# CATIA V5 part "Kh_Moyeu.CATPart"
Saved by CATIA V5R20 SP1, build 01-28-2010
Part number: Moyeu
Bounding box of the stored display mesh (mm): x -31.991 to 31.991, y -32 to 32, z -27 to 27
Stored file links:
  G:\Khaled_CFAO_2011\SIL\SIL_GR1\tmerino\Khaled\CAD_Thinkmotion\Kh_Moyeu.CATPart
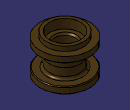
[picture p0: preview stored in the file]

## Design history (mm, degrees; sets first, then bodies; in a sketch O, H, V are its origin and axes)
Body1 (main body)
  Sketch1 on yz-plane, origin (0, 0, 0), H (0, 1, 0), V (0, 0, 1)
    line L1 (13, 0) -> (13, 15)
    point P1 (13, 0)
    point P2 (13, 15)
    line L2 (13, 15) -> (20, 15)
    point P3 (20, 15)
    line L3 (20, 15) -> (20, 27)
    point P4 (20, 27)
    line L4 (20, 27) -> (24, 27)
    point P5 (24, 27)
    line L5 (24, 27) -> (24, 21)
    point P6 (24, 21)
    line L6 (24, 21) -> (32, 21)
    point P7 (32, 21)
    line L7 (32, 21) -> (32, 13)
    point P8 (32, 13)
    line L8 (32, 13) -> (20, 13)
    point P9 (20, 13)
    line L9 (20, 13) -> (20, 0)
    point P10 (20, 0)
    point P11 (13, 0)
    point P12 (13, -15)
    point P13 (20, -15)
    point P14 (20, -27)
    point P15 (24, -27)
    point P16 (24, -21)
    point P17 (32, -21)
    point P18 (32, -13)
    point P19 (20, -13)
    point P20 (20, 0)
    line L10 (13, 0) -> (13, -15)
    line L11 (13, -15) -> (20, -15)
    line L12 (20, -15) -> (20, -27)
    line L13 (20, -27) -> (24, -27)
    line L14 (24, -27) -> (24, -21)
    line L15 (24, -21) -> (32, -21)
    line L16 (32, -21) -> (32, -13)
    line L17 (32, -13) -> (20, -13)
    line L18 (20, -13) -> (20, 0)
    distance L1 V = 13
    length L1 = 15
    distance L3 V = 20
    length L3 = 12
    length L4 = 4
    length L5 = 6
    length L6 = 8
    length L7 = 8
    length L8 = 12
    vertical: L1 V, L3 V, L5 V, L7 V, L9 V
    horizontal: L2 H, L4 H, L6 H, L8 H
    coincidence: P10 H, P1 P11, P10 P20
    symmetry: P1 P11 H, P2 P12 H, P3 P13 H, P4 P14 H, P5 P15 H, P6 P16 H, P7 P17 H, P8 P18 H, P9 P19 H, P10 P20 H, L1 L10 H, L2 L11 H, L3 L12 H, L4 L13 H, L5 L14 H, L6 L15 H, L7 L16 H, L8 L17 H, L9 L18 H
  Shaft1: profile Sketch1, axis Sketch1.V, angle 360
  Fillet1: radius 3, on edge [face of Shaft1 from Sketch1.L17 | face of Shaft1 from Sketch1.L18]; edge [face of Shaft1 from Sketch1.L9 | face of Shaft1 from Sketch1.L8]
  Chamfer1: length 2, angle 45, on edge [face of Shaft1 from Sketch1.L2 | face of Shaft1 from Sketch1.L1]; edge [face of Shaft1 from Sketch1.L10 | face of Shaft1 from Sketch1.L11]
  Chamfer2: length 1, angle 45, on edge [face of Shaft1 from Sketch1.L16 | face of Shaft1 from Sketch1.L17]; edge [face of Shaft1 from Sketch1.L8 | face of Shaft1 from Sketch1.L7]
